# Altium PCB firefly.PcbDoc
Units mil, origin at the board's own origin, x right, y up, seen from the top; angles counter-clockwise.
Board outline 3000 x 2750 mil, 2 copper layers (Top Layer, Bottom Layer); 17 components, 11 nets, 41 pads, 8 vias.
Unrouted connection lines stored in the file: 1.
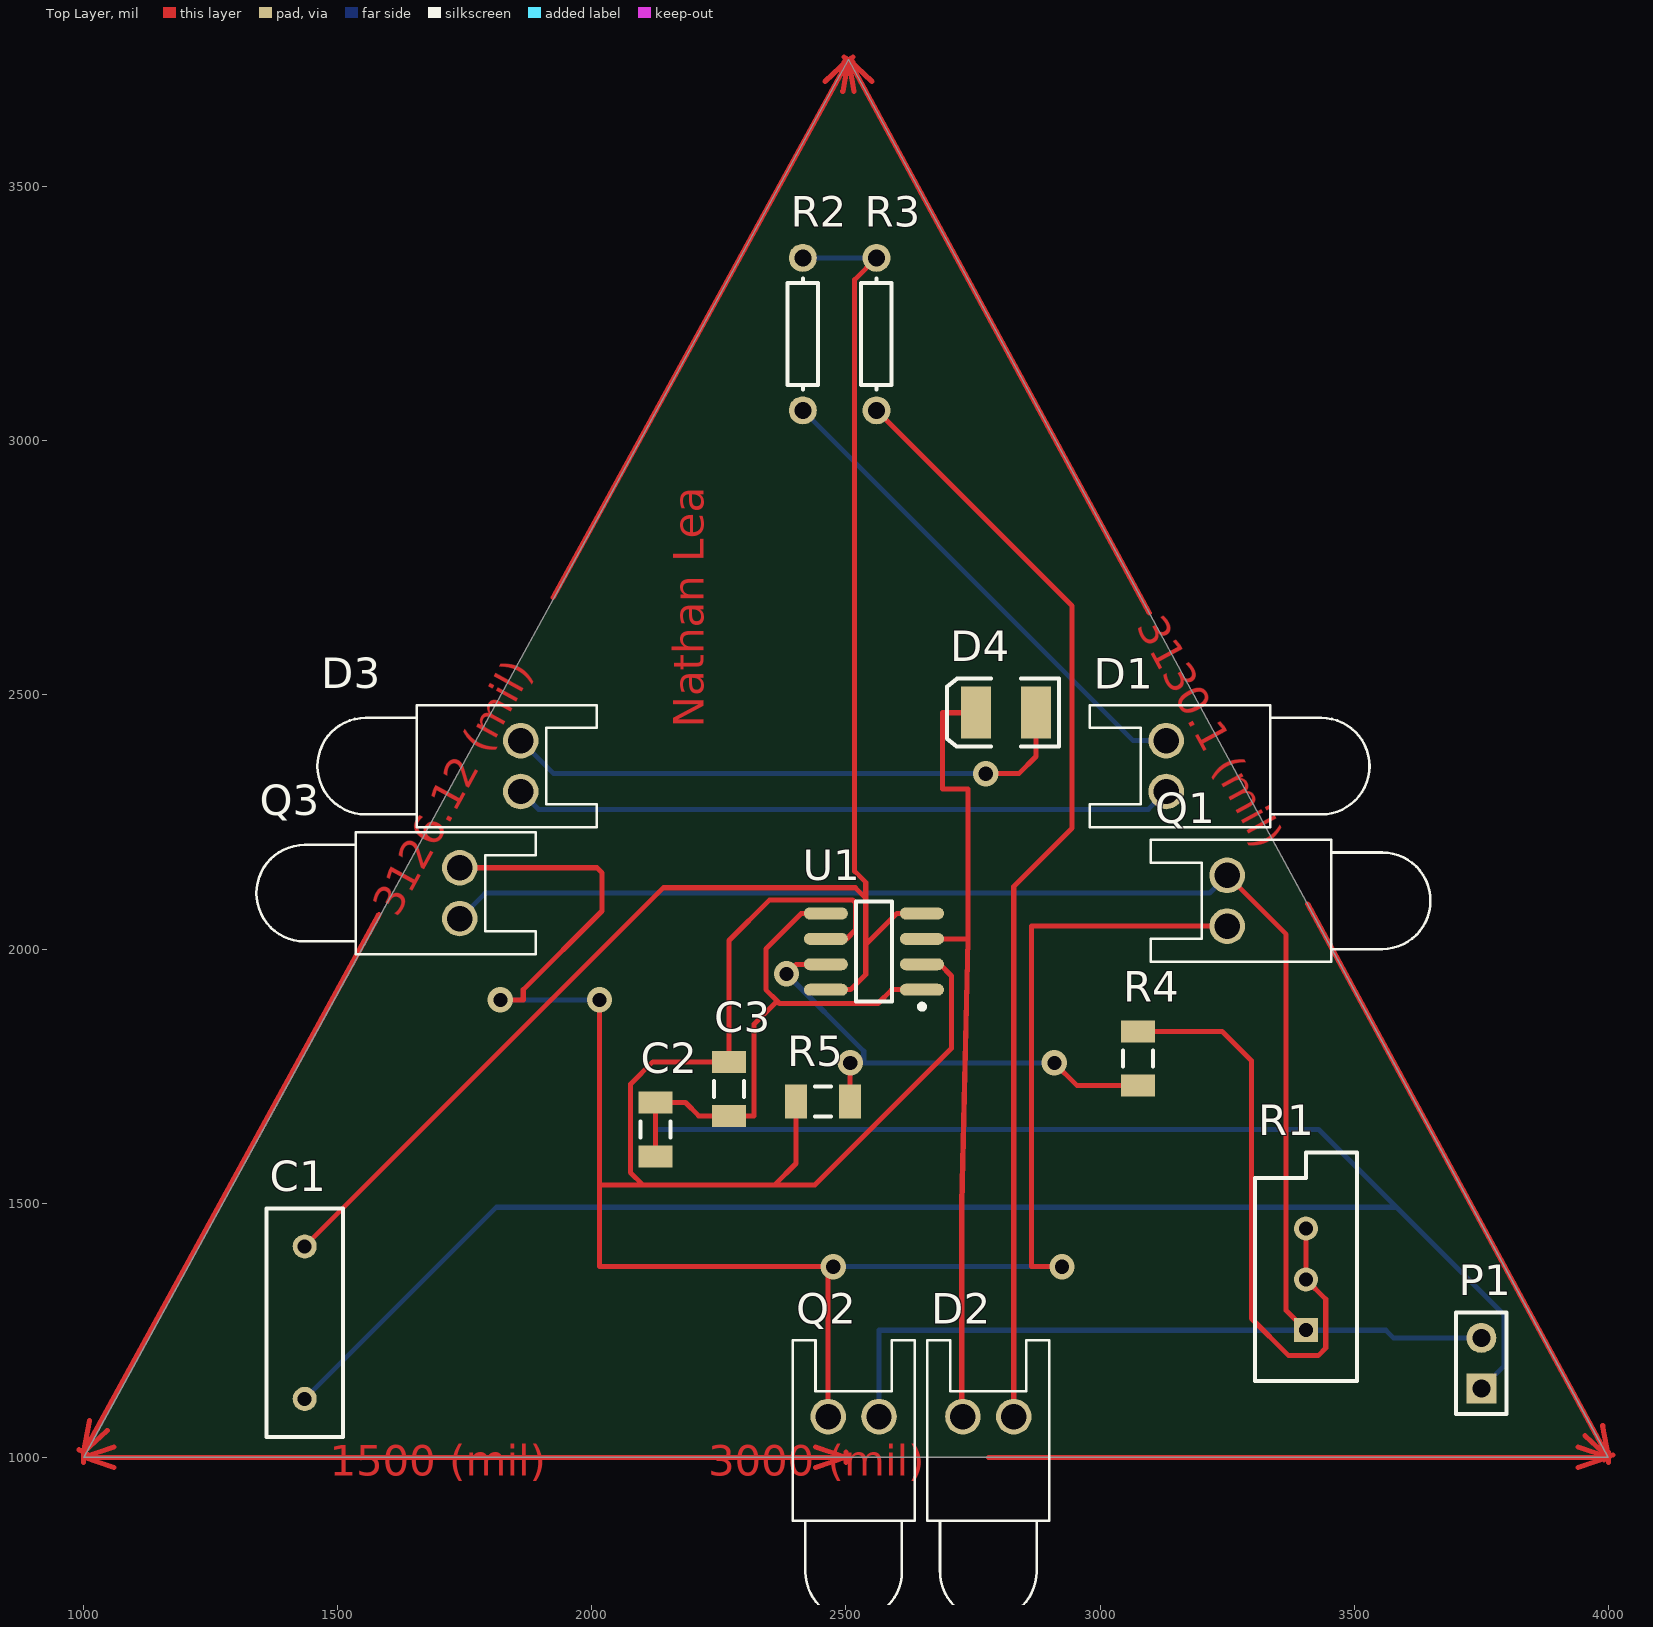
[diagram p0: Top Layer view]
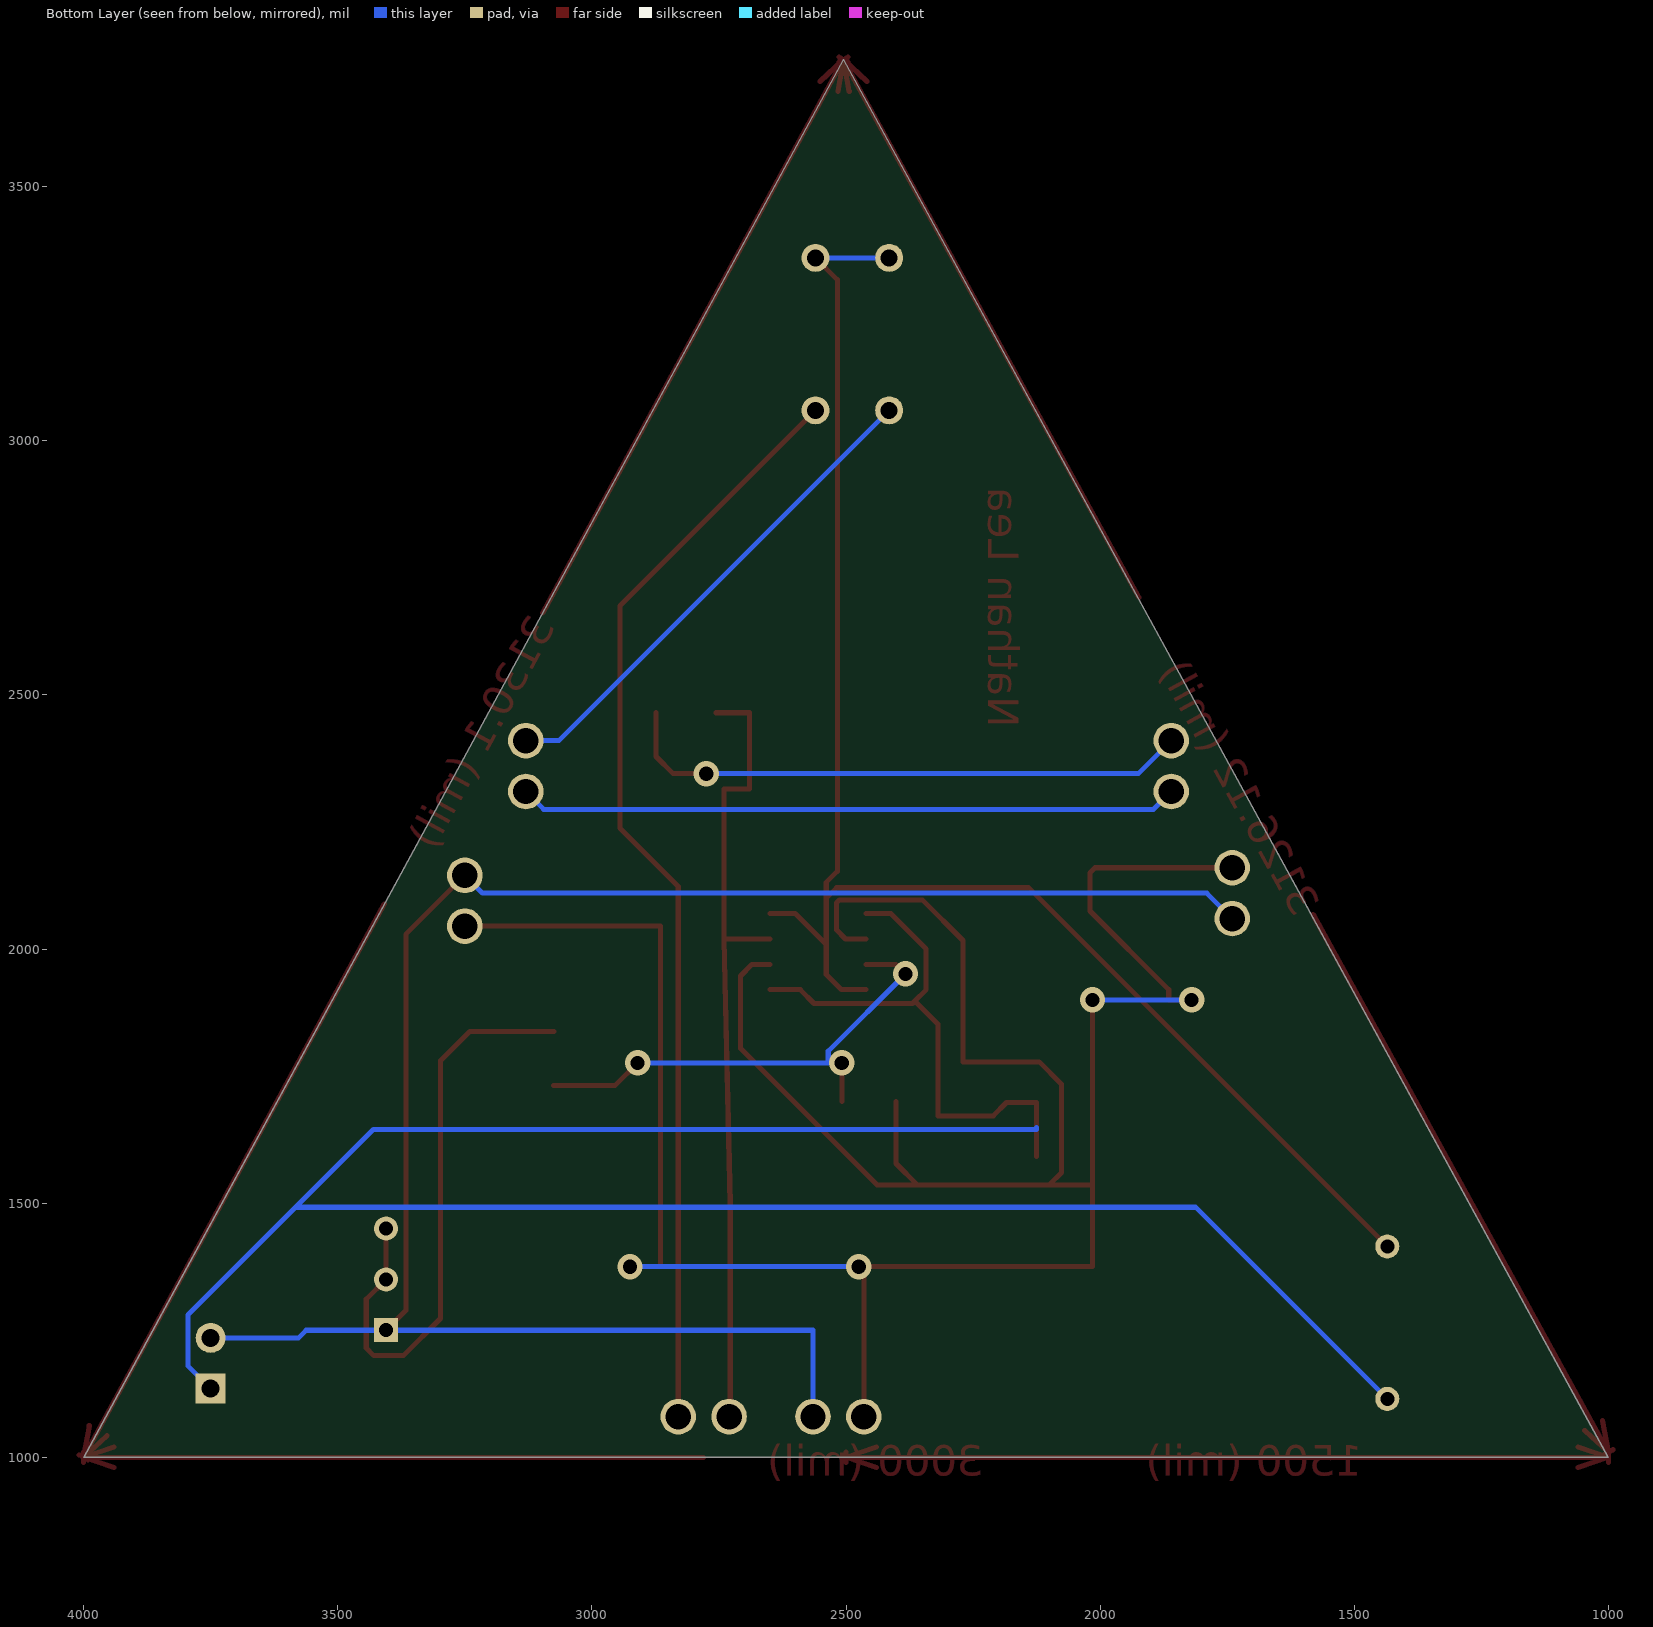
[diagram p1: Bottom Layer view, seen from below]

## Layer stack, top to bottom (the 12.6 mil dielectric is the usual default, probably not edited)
Top Solder: solder mask 0.4, Solder Resist, Dk 3.5
Top Layer: signal copper 1.4
Dielectric 1: dielectric 12.6, FR-4, Dk 4.8
Bottom Layer: signal copper 1.4
Bottom Solder: solder mask 0.4, Solder Resist, Dk 3.5

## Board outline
1000,1000 4000,1000 2505,3750

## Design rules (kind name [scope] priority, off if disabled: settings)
Clearance [All] p1: gap=10
PolygonConnect [All] p1: connectstyle=Relief reliefconductorwidth=10 reliefentries=4 polygonreliefangle="90 Angle" airgapwidth=10
RoutingVias [All] p1: holewidth=28 width=50 viastyle="Through Hole" minholewidth=28 minwidth=50 maxholewidth=28 maxwidth=50
SolderMaskExpansion [All] p1: expansion=4
Width [All] p1: maxlimit=10 minlimit=10 preferedwidth=10
30 further rules are at their usual default settings.

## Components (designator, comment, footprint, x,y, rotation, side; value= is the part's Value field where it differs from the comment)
C1 "Cap" RAD-0.3 1435,1265 r90 top
C2 "Cap" C1206 2125,1645 r90 top
C3 "Cap" C1206 2270,1725 r90 top
D1 "LED0" LED-0 3130,2360 r90 top
D2 "LED0" LED-0 2780,1080 r0 top
D3 "LED0" LED-0 1860,2360 r270 top
D4 "LED3" 3.5X2.8X1.9 2815,2465 r180 top
P1 "Header 2" HDR1X2 3750,1135 r90 top
Q1 "Photo NPN" LED-0 3250,2095 r90 top
Q2 "Photo NPN" LED-0 2515,1080 r0 top
Q3 "Photo NPN" LED-0 1740,2110 r270 top
R1 "RPot" VR5 3405,1350 r90 top
R2 "Res1" AXIAL-0.3 2415,3210 r90 top
R3 "Res1" AXIAL-0.3 2560,3210 r90 top
R4 "Res3" C1206 3075,1785 r90 top
R5 "Res3" C1206 2455,1700 r0 top
U1 "LM555CM" M08A_N 2555,1995 r180 top

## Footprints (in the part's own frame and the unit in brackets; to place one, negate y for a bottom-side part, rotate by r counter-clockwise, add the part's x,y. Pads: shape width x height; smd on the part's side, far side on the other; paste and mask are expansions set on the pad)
3.5X2.8X1.9 [mm] "SM LED; 2 C-Bend Leads; Body 3.5 x 2.8 x 1.9 mm, inc leads (LxWxH typ)"
  rect 1.5x2.6 smd: 1(-1.5,0) 2(1.5,0)
  silkscreen extent -2.65,-1.7 2.95,1.7
AXIAL-0.3 [mm] "Axial Device, Thru-Hole; 2 Leads; 0.3 in Pin Spacing"
  round 1.4 hole 0.85: 1(-3.81,0) 2(3.81,0)
  silkscreen extent -2.77,-0.76 2.77,0.76
C1206 [mm] "Chip Capacitor, Body 3.2x1.6mm, IPC High Density"
  rect 1.1x1.7 smd: 1(-1.35,0) 2(1.35,0)
  silkscreen extent -0.4,-0.75 0.4,0.75, body extent -1.7,-0.9 1.7,0.9, height 1.3
HDR1X2 [mm] "Connector; Header; 2 Position"
  rect 1.5x1.5 hole 0.9: 1(0,0)
  round 1.5 hole 0.9: 2(2.54,0)
  silkscreen extent -1.27,-1.27 3.81,1.27
LED-0 [mil] "LED; 2 Leads"
  round 70 hole 50: 1(50,0) 2(-50,0)
  silkscreen extent -120,-400 120,150
M08A_N [mm] "SOIC, 8-Leads, Body 4.9x3.9mm, Pitch 1.27mm, IPC Medium Density"
  oval 2.2x0.6 smd: 1(-2.4,1.905) 2(-2.4,0.635) 3(-2.4,-0.635) 4(-2.4,-1.905) 5(2.4,-1.905) 6(2.4,-0.635) 7(2.4,0.635) 8(2.4,1.905)
  silkscreen extent -2.53,-2.5 0.9,2.88, body extent -2,-2.5 2,2.5, height 1.75
RAD-0.3 [mm] "Radial Cap, Thru-Hole; 2 Leads; 0.3 in Pin Spacing"
  round 1.2 hole 0.7: 1(-3.81,0) 2(3.81,0)
  silkscreen extent -5.71,-1.91 5.71,1.91
VR5 [mm] "Thru-Hole; 3 Leads"
  rect 1.2x1.2 hole 0.7: 1(-2.54,0)
  round 1.2 hole 0.7: 2(0,0) 3(2.54,0)
  silkscreen extent -5.08,-2.54 6.35,2.54

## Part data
C1 C2 C3: "Capacitor"
D1 D2 D3: "Typical INFRARED GaAs LED"
D4: "Typical BLUE SiC LED"
P1: "Header, 2-Pin"
Q1 Q2 Q3: "NPN Phototransistor"
R1: "Potentiometer"
R2 R3 R4 R5: "Resistor"
U1: "Timer, 8-pin Narrow SOIC"

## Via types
v1: diameter 50, hole 28, Top Layer to Bottom Layer, 8 vias

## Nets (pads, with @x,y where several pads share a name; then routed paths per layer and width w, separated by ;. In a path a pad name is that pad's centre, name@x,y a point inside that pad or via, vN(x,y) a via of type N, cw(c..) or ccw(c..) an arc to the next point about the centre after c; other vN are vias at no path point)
NetC1_1: C1.1 C2.1 C2.2 C3.1 P1.1 U1.1 U1.5 | length 5405.9
  Top Layer w10: C2.1 C2.2 2184,1698.15 2210.3,1671.85 C3.1 2319,1671.85 2319,1852 2364.6,1897.6 ; U1.5 2412,2070 2342.2,2000.2 2342.2,1920 2364.6,1897.6 ; U1.1 2590,1920 2563,1893 2369.2,1893 2364.6,1897.6
  Bottom Layer w10: C1.1 1812,1492 3583,1492 ; 2125,1649 2125,1645 3430,1645 3583,1492 ; P1.1 3795,1180 3795,1280 3583,1492
NetC1_2: C1.2 R2.2 R3.2 U1.4 U1.8 | length 3213.4
  Top Layer w10: C1.2 2140.65,2120.65 2518.17,2120.65 2538.82,2100 ; U1.8 2509,1920 2538.82,1949.82 2538.82,2008.82 ; R3.2 2517,3317 2517,2153 2538.82,2131.18 2538.82,2100 ; U1.4 2600,2070 2538.82,2008.82 ; 2538.82,2008.82 2538.82,2100
  Bottom Layer w10: R2.2 R3.2
NetC3_2: C3.2 R5.1 U1.2 U1.6 | length 2172.7
  Top Layer w10: R5.1 2401.85,1577.85 2360,1536 ; U1.6 2501,2020 2518.82,2037.82 2518.82,2091 2513.01,2096.81 2350,2096.81 2270,2016.81 C3.2 2120,1778.15 2076,1734.15 2076,1560 2100,1536 2360,1536 ; U1.2 2684.8,1970 2707.8,1947 2707.8,1804.8 2439,1536 2360,1536
NetD1_1: D1.1 R2.1 | length 984.2
  Bottom Layer w10: R2.1 3065,2410 D1.1
NetD1_2: D1.2 D3.1 | length 1299.1
  Bottom Layer w10: D3.1 1895.14,2274.86 3094.86,2274.86 D1.2
NetD2_1: D2.1 R3.1 | length 2187.1
  Top Layer w10: R3.1 2945,2675 2945,2238 2830,2123 D2.1
NetD2_2: D2.2 D4.2 U1.3 | length 1591.6
  Top Layer w10: U1.3 2740,2020 ; D2.2@2727.8,1080 2727.8,1497.8 2740,2020 ; D4.2 2690,2465 2690,2315 2740,2315 2740,2020
NetD3_2: D3.2 D4.1 | length 1141
  Top Layer w10: v1(2775,2345) 2840,2345 2874.06,2379.06 D4.1
  Bottom Layer w10: D3.2 1925,2345 v1(2775,2345)
NetP1_2: P1.2 Q1.1 Q2.1 Q3.1 R1.1 | length 3865.6
  Top Layer w10: Q1.1 3366,2029 3366,1289 R1.1
  Bottom Layer w10: Q3.1 1790,2110 3215,2110 Q1.1 ; Q2.1 2565,1250 R1.1 3562,1250 3577,1235 P1.2
NetR1_2: R1.2 R1.3 R4.2 | length 1187.8
  Top Layer w10: R4.2 3240,1838.15 3298,1780.15 3298,1273 3371,1200 3429,1200 3444,1215 3444,1311 R1.2 R1.3
NetR4_1: R4.1 R5.2 U1.7 | length 957.6
  Top Layer w10: v1(2383,1951) 2402,1970 U1.7 ; R5.2 v1(2508.15,1776) ; v1(2910,1776) 2954.15,1731.85 R4.1
  Bottom Layer w10: v1(2383,1951) 2535,1799 2535,1776 v1(2910,1776)
pads on no net: Q1.2 Q2.2 Q3.2
copper on no net: | length 13228.3
  Top Layer w10: 991.24,1014.81 1008.76,1005.19 ; 1011.36,1072.22 1000,1010 ; 1046.42,1052.96 1000,1010 ; 1474.08,1000 1000,1000 ; 1581.16,2068.07 1000,1010 ; 1740,2160 2010,2160 2020,2150 2020,2075 1865,1920 1865,1900 v1(1820,1900) ; 1923.84,2691.93 2505,3750 ; v1(2015,1900) 2015,1375 v1(2475,1375) 2465,1375 2465,1080 ; 2016,1536 2100,1536 ; 2025.92,1000 2500,1000 ; 2219.09,1000 1000,1000 ; 2440,980 2500,1000 ; 2440,1020 2500,1000 ; 2458.58,3707.04 2505,3750 ; 2493.64,3687.78 2505,3750 ; 2496.21,3745.22 2513.79,3754.78 ; 2496.24,3754.81 2513.76,3745.19 ; 2500,990 2500,1010 ; 2516.09,3687.73 2505,3750 ; 2551.23,3706.84 2505,3750 ; 2780.91,1000 4000,1000 ; v1(2925,1375) 2865,1375 2865,2045 3250,2045 ; 3096.84,2661.32 2505,3750 ; 3408.16,2088.68 4000,1000 ; 3940,980 4000,1000 ; 3940,1020 4000,1000 ; 3953.77,1043.16 4000,1000 ; 3988.91,1062.27 4000,1000 ; 3991.21,995.22 4008.79,1004.78 ; 4000,990 4000,1010 ; 1000,1000 1060,980 1000,1000 ; 1000,1000 1060,1020 1000,1000 ; 1000,1010 1000,990 1000,1010
  Bottom Layer w10: v1(1820,1900) v1(2015,1900) ; v1(2475,1375) v1(2925,1375)

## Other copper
Top Layer:
  text "3130.1 (mil)" at 3070,2635.35 h60 r298.53
  text "Nathan Lea" at 2220,2435 h60 r90
  text "3126.12 (mil)" at 1617.52,2059.51 h60 r61.22
  text "1500 (mil)" at 1484.08,964.01 h60
  text "3000 (mil)" at 2229.09,964.01 h60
